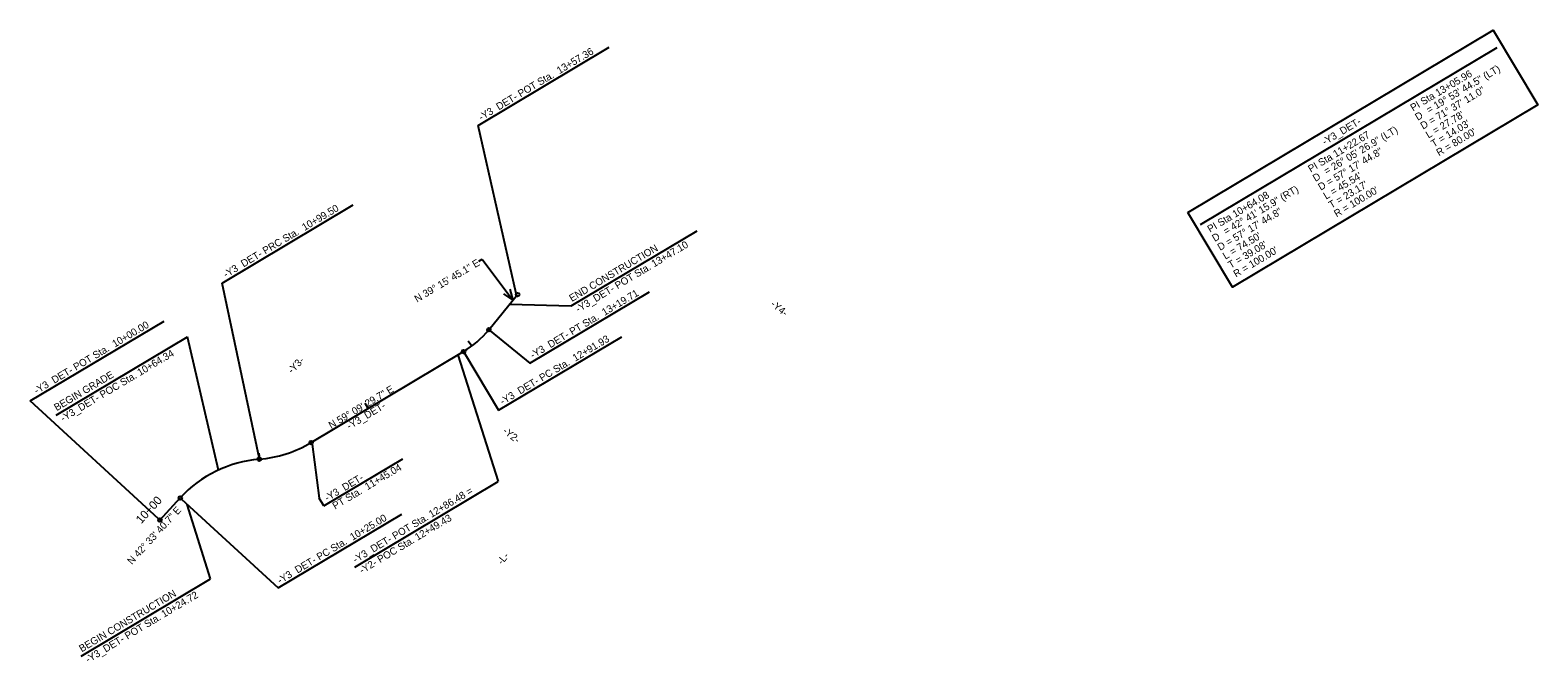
# Model space of a CAD drawing. Extents: x 1487048 to 1489513, y 498946 to 500108.
# Drawn here: x 1488265 to 1489513, y 498946 to 499468 of the extents above; entities that cross this region are included whole.
import ezdxf

# ---------------------------------------------------------------- set-up
doc = ezdxf.new("R2010")
doc.units = 0
for name, color, linetype in [('Prop North Arrow NAD83 for Plan Sheets CELL', 7, 'Continuous'), ('Scratch_Level_5', 7, 'Continuous'), ('Sheet Block Title CELL', 7, 'Continuous'), ('Sheet Cutting Line CELL', 7, 'Continuous'), ('Sheet Plot Border Inside CELL', 7, 'Continuous'), ('Sheet Plot Border Outside CELL', 7, 'Continuous'), ('Sheet Sticker Exception Certification CELL', 7, 'Continuous')]:
    doc.layers.add(name, color=color, linetype=linetype)

msp = doc.modelspace()

# ---------------------------------------------------------------- linework, layer by layer
at = {"layer": 'Prop North Arrow NAD83 for Plan Sheets CELL'}
msp.add_line((1488372.5, 499062.5), (1488366.6, 499067.9), dxfattribs=at)
at = {"layer": 'Sheet Block Title CELL'}
for p, q in [((1488630.6, 499206.5), (1488627.6, 499210.5)), ((1488544.9, 499154.9), (1488542.4, 499159.2)), ((1488455.2, 499112.9), (1488454.8, 499117.9))]:
    msp.add_line(p, q, dxfattribs=at)
at = {"layer": 'Sheet Cutting Line CELL'}
msp.add_line((1489233.9, 499307.2), (1489479.4, 499453.7), dxfattribs=at)
msp.add_lwpolyline([(1489223.5, 499317.1), (1489476.2, 499468), (1489513.1, 499406.3), (1489260.4, 499255.4)], close=True, dxfattribs=at)
at = {"layer": 'Sheet Plot Border Inside CELL'}
for p, q in [((1488644.8, 499220.1), (1488668.6, 499249.2)), ((1488497.7, 499126.7), (1488623.9, 499202)), ((1488372.5, 499062.5), (1488389.4, 499080.9))]:
    msp.add_line(p, q, dxfattribs=at)
for centre, radius, start, end in [((1488582.8, 499270.7), 80, 300.8418, 320.7375), ((1488446.5, 499212.6), 100, 274.7509, 300.8418), ((1488463, 499013.2), 100, 94.7509, 137.4387)]:
    msp.add_arc(centre, radius, start, end, dxfattribs=at)
at = {"layer": 'Sheet Plot Border Outside CELL'}
for p, q in [((1488636.6, 499276.9), (1488639.4, 499278.5)), ((1488639.4, 499278.5), (1488664.7, 499244.5)), ((1488656.8, 499249.9), (1488664.7, 499244.5)), ((1488662.1, 499253.7), (1488664.7, 499244.5))]:
    msp.add_line(p, q, dxfattribs=at)
at = {"layer": 'Sheet Sticker Exception Certification CELL'}
for p, q in [((1488636, 499389.1), (1488744.5, 499453.9)), ((1488667.4, 499250.2), (1488636, 499389.1)), ((1488424, 499258.7), (1488532.4, 499323.4)), ((1488712.9, 499239.8), (1488817.2, 499302)), ((1488454.6, 499114.4), (1488424, 499258.7)), ((1488678.8, 499192.3), (1488777.8, 499251.4)), ((1488662.1, 499241.3), (1488712.9, 499239.8)), ((1488265.1, 499161.1), (1488376.1, 499227.3)), ((1488286.5, 499149.3), (1488395.3, 499214.3)), ((1488420.9, 499103.9), (1488395.3, 499214.3)), ((1488645.9, 499219.1), (1488678.8, 499192.3)), ((1488652.9, 499153.4), (1488754.8, 499214.2)), ((1488619.2, 499199.2), (1488652.5, 499094.4)), ((1488624.6, 499200.7), (1488652.9, 499153.4)), ((1488371.4, 499063.5), (1488265.1, 499161.1)), ((1488498.5, 499125.4), (1488504.3, 499080.7)), ((1488508.2, 499074.2), (1488573.5, 499113.2)), ((1488533.9, 499023.6), (1488652.5, 499094.4)), ((1488390.5, 499079.9), (1488470.5, 499006.4)), ((1488414.3, 499013.8), (1488395, 499075.3)), ((1488395, 499075.3), (1488395.2, 499074.7)), ((1488508.2, 499074.2), (1488504.3, 499080.7)), ((1488470.5, 499006.4), (1488572.8, 499067.5)), ((1488307.2, 498949.8), (1488414.3, 499013.8))]:
    msp.add_line(p, q, dxfattribs=at)
for centre in [(1488668.6, 499249.2), (1488644.8, 499220.1), (1488623.9, 499202), (1488497.7, 499126.7), (1488454.7, 499112.9), (1488389.4, 499080.9), (1488372.5, 499062.5)]:
    msp.add_circle(centre, 1.5, dxfattribs=at)

# ---------------------------------------------------------------- texts
at = {"layer": 'Scratch_Level_5'}
msp.add_text('10+00', height=7, rotation=47.4387, dxfattribs=at).set_placement((1488357, 499059))
at = {"layer": 'Sheet Cutting Line CELL'}
for s, p in [('PI Sta 13+05.96', (1489409.8, 499400.7)), ('= 19%%d 53\' 44.5" (LT)', (1489423.1, 499398.9)), ('D = 71%%d 37\' 11.0"', (1489418.1, 499385.7)), ('D', (1489413.7, 499393)), ("L = 27.78'", (1489422.5, 499378.3)), ('PI Sta 11+22.67', (1489325.1, 499350.1)), ('-Y3_DET-', (1489336.8, 499372.6)), ('= 26%%d 05\' 26.9" (LT)', (1489338.3, 499348.3)), ("T = 14.03'", (1489426.9, 499370.9)), ("R = 80.00'", (1489431.3, 499363.6)), ('D = 57%%d 17\' 44.8"', (1489333.4, 499335.1)), ('D', (1489329, 499342.4)), ("L = 45.54'", (1489337.8, 499327.7)), ('= 42%%d 41\' 15.9" (RT)', (1489255, 499298.5)), ("T = 23.17'", (1489342.2, 499320.3)), ("R = 100.00'", (1489346.6, 499313)), ('PI Sta 10+64.08', (1489241.8, 499300.3)), ('D = 57%%d 17\' 44.8"', (1489250.1, 499285.3)), ('D', (1489245.7, 499292.7)), ("L = 74.50'", (1489254.5, 499278)), ("T = 39.08'", (1489258.9, 499270.6)), ("R = 100.00'", (1489263.3, 499263.2))]:
    msp.add_text(s, height=6, rotation=30.8418, dxfattribs=at).set_placement(p)
at = {"layer": 'Sheet Plot Border Outside CELL'}
for s, rotation, p in [('N 39%%d 15\' 45.1" E', 30.8418, (1488585.4, 499242.5)), ('-Y4-', 321.0285, (1488877.6, 499240.3)), ('-Y3-', 45.4445, (1488481.8, 499183.3)), ('N 59%%d 09\' 29.7" E', 30.8418, (1488514.3, 499137.9)), ('-Y3_DET-', 30.8418, (1488529.3, 499137.3)), ('-Y2-', 321.0285, (1488655.8, 499135.3)), ('N 42%%d 33\' 40.7" E', 47.4387, (1488349.3, 499025.3)), ('-L-', 51.9837, (1488655.8, 499025.1))]:
    msp.add_text(s, height=6, rotation=rotation, dxfattribs=at).set_placement(p)
at = {"layer": 'Sheet Sticker Exception Certification CELL'}
for s, p in [('-Y3_DET- POT Sta.  13+57.36', (1488638.5, 499392.9)), ('-Y3_DET- PRC Sta.  10+99.50', (1488427.2, 499262.9)), ('END CONSTRUCTION', (1488713.5, 499243)), ('-Y3_DET- POT Sta. 13+47.10', (1488718.8, 499234.1)), ('-Y3_DET- PT Sta.  13+19.71', (1488681.2, 499196)), ('-Y3_DET- POT Sta.  10+00.00', (1488270.5, 499166.6)), ('-Y3_DET- PC Sta.  12+91.93', (1488656.2, 499157.7)), ('-Y3_DET- POC Sta. 10+64.34', (1488292.4, 499143.7)), ('BEGIN GRADE', (1488287.1, 499152.6)), ('-Y3_DET-', (1488511, 499077.8)), (' PT Sta.  11+45.04', (1488515.6, 499070)), ('-Y3_DET- POT Sta. 12+86.48 = ', (1488534.5, 499026.8)), ('-Y3_DET- PC Sta.  10+25.00', (1488471.9, 499009.5)), ('-Y2- POC Sta. 12+49.43', (1488539.8, 499017.9)), ('BEGIN CONSTRUCTION', (1488307.8, 498953)), ('-Y3_DET- POT Sta. 10+24.72', (1488313.1, 498944.1))]:
    msp.add_text(s, height=6, rotation=30.8418, dxfattribs=at).set_placement(p)

doc.saveas('drawing.dxf')
